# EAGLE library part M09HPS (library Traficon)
SUB-D
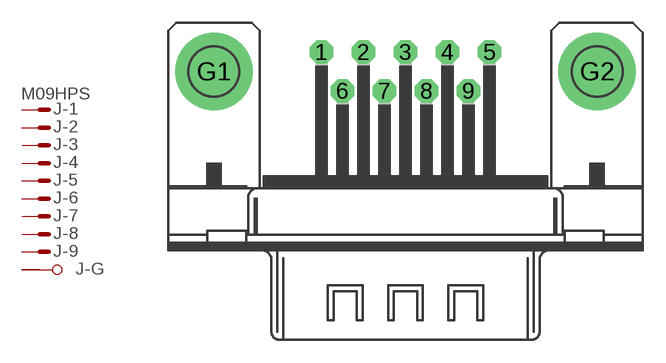
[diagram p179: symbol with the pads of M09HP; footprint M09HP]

Designator prefix J; gates -2=M-1 -3=M-1 -4=M-1 -5=M-1 -6=M-1 -7=M-1 -8=M-1 -9=M-1 -G=GND -1=MV

## M09HPS  [M09HP]
1  -1:M  pas
2  -2:M  pas
3  -3:M  pas
4  -4:M  pas
5  -5:M  pas
6  -6:M  pas
7  -7:M  pas
8  -8:M  pas
9  -9:M  pas
G1  -G:G1  pas
G2  -G:G2  pas

## Footprint M09HP (pad centres in mm)
SUB-D
drill 1.016 octagon: 1 -5.486,1.27; 2 -2.743,1.27; 3 0,1.27; 4 2.743,1.27; 5 5.486,1.27; 6 -4.115,-1.27; 7 -1.372,-1.27; 8 1.372,-1.27; 9 4.115,-1.27
drill 3.302 pad 5.08 round: G1 -12.522,0; G2 12.522,0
